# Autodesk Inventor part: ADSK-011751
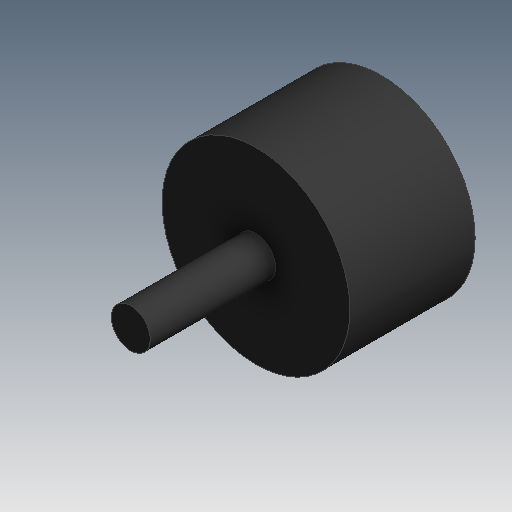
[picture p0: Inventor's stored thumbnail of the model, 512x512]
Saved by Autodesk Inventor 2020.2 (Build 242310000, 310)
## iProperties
Created: 1999-08
Part Number: ADSK-011751
Material: Pearson Nylatron
Description: BUMPER,RUBBER,1.500 DIA WITH, 5/16-18
Document SubType Name: Modeling
Designer: MP
Density: 1.13867 g/cm^3
Appearance: Rubber-Black
Mass: 34.4051 g
Surface Area: 59.5381 cm^2
Volume: 30.2152 cm^3
Control State: 0
Master: False
Checked Out: False
Shininess: 10.0
Length Units: 11272
Angle Units: 11279
Time Units: 11290
Mass Units: 11286
Length Display Precision: 3
Angle Display Precision: 2
Compacted: True
Dimensions: 1,5x2x1,5 in
Mass: 0,076 lb
VLT_Material: Pearson Nylatron
Density: 1.13867
Volumn: 30.215204497714613
Area: 59.53812879395598
PropertySet Name: Model Information
Title: A100202
Author: MP
Revision Number: -
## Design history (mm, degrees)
node "Extrusion1" dims "d1" = 25.4, "d2" = 0
node "Extrusion2" dims "d4" = 25.4, "d5" = 0
node "Solide1"
node "Corps solides"
node "Corps surfaciques"
sketch "Sketch1"
  geometry: C1 r 19.05 at (0, 0); 1 further point
  constraints: 1 centre point, 1 coincident
  dimensions: "d0" = 38.1 diameter of C1
sketch "Sketch2"
  geometry: C1 r 19.05 at (0, 0) reference; C2 r 3.969 at (0, 0)
  constraints: 1 centre point, 1 coincident
  dimensions: "d3" = 7.9375 diameter of C2
